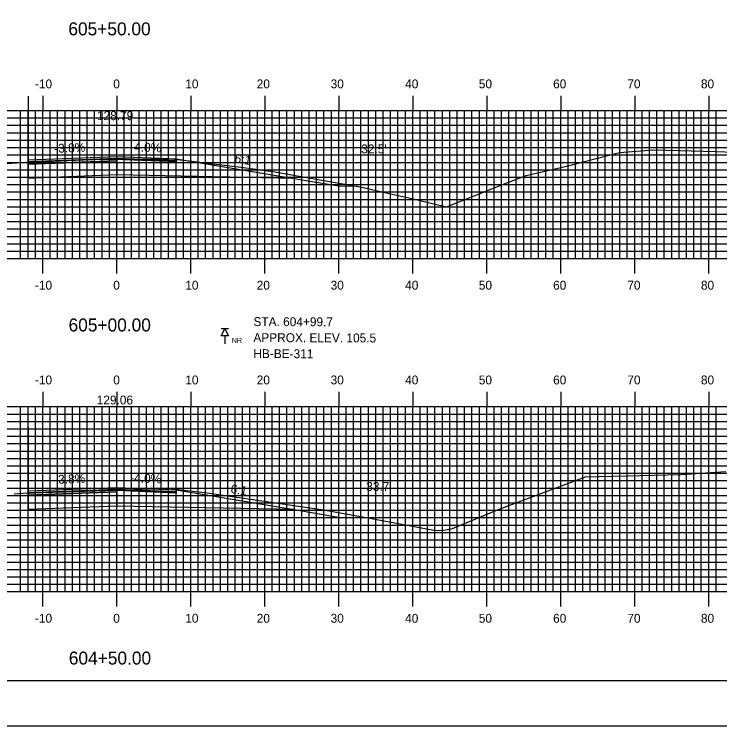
# Model space of a CAD drawing. Extents: x 842175 to 842518, y 363538 to 363758.
# Drawn here: x 842327 to 842422.4, y 363537.6 to 363633.7 of the extents above; entities that cross this region are included whole.
import ezdxf

# ---------------------------------------------------------------- set-up
doc = ezdxf.new("R2010")
doc.units = 0
for name, color, linetype in [('ANNOTATION', 7, 'Continuous'), ('BORDER', 7, 'Continuous'), ('BORING - NO REFUSAL', 7, 'Continuous'), ('D_Roadway_Centerline', 7, 'Continuous'), ('D_Roadway_Centerline_Text', 7, 'Continuous'), ('D_Roadway_Edge_Shoulder', 7, 'Continuous'), ('D_Roadway_Edge_TW', 7, 'Continuous'), ('D_Roadway_FinishedGrade', 7, 'Continuous'), ('D_Roadway_Pavement', 7, 'Continuous'), ('D_Roadway_SlopeLines', 7, 'Continuous'), ('D_Roadway_SubGrade', 7, 'Continuous'), ('D_Text_Standard', 7, 'Continuous'), ('H_V ANNOTATION', 7, 'Continuous'), ('M_Roadway_Centerline', 7, 'Continuous'), ('MAJOR', 7, 'Continuous'), ('MINOR', 7, 'Continuous'), ('PLOT BOUNDARY', 7, 'Continuous'), ('S_Roadway_Centerline', 7, 'Continuous')]:
    doc.layers.add(name, color=color, linetype=linetype)

msp = doc.modelspace()

# ---------------------------------------------------------------- linework, layer by layer
at = {"layer": 'BORDER'}
msp.add_lwpolyline([(842191.285, 363543.721), (842511.285, 363543.721), (842511.285, 363753.721), (842191.285, 363753.721)], close=True, dxfattribs=at)
at = {"layer": 'BORING - NO REFUSAL'}
for p, q in [((842355.965, 363591.221), (842355.005, 363591.221)), ((842355.485, 363590.261), (842355.485, 363589.202))]:
    msp.add_line(p, q, dxfattribs=at)
msp.add_lwpolyline([(842355.485, 363591.221), (842355.965, 363590.261), (842355.005, 363590.261)], close=True, dxfattribs=at)
at = {"layer": 'D_Roadway_Centerline'}
for points in [[(842328.885, 363614.056), (842340.885, 363614.512), (842348.885, 363614.192), (842349.971, 363614.011), (842364.839, 363611.533)], [(842328.885, 363569.328), (842340.885, 363569.784), (842348.885, 363569.464), (842364.839, 363566.805)]]:
    msp.add_lwpolyline(points, dxfattribs=at)
at = {"layer": 'D_Roadway_Edge_Shoulder'}
for points in [[(842340.885, 363614.512), (842348.885, 363614.192), (842348.885, 363613.942), (842340.885, 363614.262)], [(842340.885, 363569.784), (842348.885, 363569.464), (842348.885, 363569.214), (842340.885, 363569.534)]]:
    msp.add_lwpolyline(points, close=True, dxfattribs=at)
at = {"layer": 'D_Roadway_Edge_TW'}
for points in [[(842328.885, 363614.056), (842340.885, 363614.512), (842340.885, 363614.262), (842328.885, 363613.806)], [(842328.885, 363569.328), (842340.885, 363569.784), (842340.885, 363569.534), (842328.885, 363569.078)]]:
    msp.add_lwpolyline(points, close=True, dxfattribs=at)
for points in [[(842328.885, 363614.056), (842328.885, 363613.806)], [(842328.885, 363569.328), (842328.885, 363569.078)]]:
    msp.add_lwpolyline(points, dxfattribs=at)
at = {"layer": 'D_Roadway_FinishedGrade'}
for points in [[(842364.839, 363611.533), (842370.839, 363610.533), (842373.407, 363610.482)], [(842364.839, 363566.805), (842370.839, 363565.805), (842374.678, 363565.728)]]:
    msp.add_lwpolyline(points, dxfattribs=at)
at = {"layer": 'D_Roadway_Pavement'}
for points in [[(842328.885, 363613.806), (842340.885, 363614.262), (842340.885, 363613.929), (842328.885, 363613.473)], [(842340.885, 363614.262), (842348.885, 363613.942), (842348.885, 363613.776), (842340.885, 363614.096)], [(842328.885, 363569.078), (842340.885, 363569.534), (842340.885, 363569.201), (842328.885, 363568.745)], [(842340.885, 363569.534), (842348.885, 363569.214), (842348.885, 363569.047), (842340.885, 363569.367)]]:
    msp.add_lwpolyline(points, close=True, dxfattribs=at)
for points in [[(842328.885, 363613.806), (842328.885, 363613.473)], [(842340.885, 363614.262), (842340.885, 363613.929)], [(842340.885, 363614.262), (842340.885, 363613.929)], [(842340.885, 363569.534), (842340.885, 363569.201)], [(842340.885, 363569.534), (842340.885, 363569.201)], [(842328.885, 363569.078), (842328.885, 363568.745)]]:
    msp.add_lwpolyline(points, dxfattribs=at)
at = {"layer": 'D_Roadway_SlopeLines'}
msp.add_lwpolyline([(842348.885, 363614.192), (842349.971, 363614.011)], dxfattribs=at)
at = {"layer": 'D_Roadway_SubGrade'}
for p, q in [((842328.885, 363622.654), (842328.885, 363611.556)), ((842328.885, 363577.925), (842328.885, 363566.828))]:
    msp.add_line(p, q, dxfattribs=at)
for points in [[(842328.885, 363613.473), (842340.885, 363613.929), (842340.885, 363612.012), (842328.885, 363611.556)], [(842340.885, 363613.929), (842340.885, 363614.262), (842348.885, 363613.942), (842348.885, 363614.192), (842364.839, 363611.533), (842340.885, 363612.012)], [(842340.885, 363569.201), (842340.885, 363569.534), (842348.885, 363569.214), (842348.885, 363569.464), (842364.839, 363566.805), (842340.885, 363567.284)], [(842328.885, 363568.745), (842340.885, 363569.201), (842340.885, 363567.284), (842328.885, 363566.828)]]:
    msp.add_lwpolyline(points, close=True, dxfattribs=at)
for points in [[(842328.885, 363613.473), (842328.885, 363611.556)], [(842328.885, 363568.745), (842328.885, 363566.828)]]:
    msp.add_lwpolyline(points, dxfattribs=at)
at = {"layer": 'MAJOR'}
for p, q in [((842330.885, 363622.725), (842330.885, 363620.721)), ((842340.885, 363622.725), (842340.885, 363620.721)), ((842350.885, 363622.725), (842350.885, 363620.721)), ((842360.885, 363622.725), (842360.885, 363620.721)), ((842370.885, 363622.725), (842370.885, 363620.721)), ((842380.885, 363622.725), (842380.885, 363620.721)), ((842390.885, 363622.725), (842390.885, 363620.721)), ((842400.885, 363622.725), (842400.885, 363620.721)), ((842410.885, 363622.725), (842410.885, 363620.721)), ((842420.885, 363622.725), (842420.885, 363620.721)), ((842200.885, 363620.721), (842480.885, 363620.721)), ((842200.885, 363620.721), (842480.885, 363620.721)), ((842330.885, 363600.721), (842330.885, 363620.721)), ((842340.885, 363600.721), (842340.885, 363620.721)), ((842350.885, 363600.721), (842350.885, 363620.721)), ((842360.885, 363600.721), (842360.885, 363620.721)), ((842370.885, 363600.721), (842370.885, 363620.721)), ((842380.885, 363600.721), (842380.885, 363620.721)), ((842390.885, 363600.721), (842390.885, 363620.721)), ((842400.885, 363600.721), (842400.885, 363620.721)), ((842410.885, 363600.721), (842410.885, 363620.721)), ((842420.885, 363600.721), (842420.885, 363620.721)), ((842200.885, 363615.721), (842480.885, 363615.721)), ((842200.885, 363610.721), (842480.885, 363610.721)), ((842200.885, 363605.721), (842480.885, 363605.721)), ((842200.885, 363600.721), (842480.885, 363600.721)), ((842200.885, 363600.721), (842480.885, 363600.721)), ((842330.885, 363598.717), (842330.885, 363600.721)), ((842340.885, 363598.717), (842340.885, 363600.721)), ((842350.885, 363598.717), (842350.885, 363600.721)), ((842360.885, 363598.717), (842360.885, 363600.721)), ((842370.885, 363598.717), (842370.885, 363600.721)), ((842380.885, 363598.717), (842380.885, 363600.721)), ((842390.885, 363598.717), (842390.885, 363600.721)), ((842400.885, 363598.717), (842400.885, 363600.721)), ((842410.885, 363598.717), (842410.885, 363600.721)), ((842420.885, 363598.717), (842420.885, 363600.721)), ((842330.885, 363582.725), (842330.885, 363580.721)), ((842340.885, 363582.725), (842340.885, 363580.721)), ((842350.885, 363582.725), (842350.885, 363580.721)), ((842360.885, 363582.725), (842360.885, 363580.721)), ((842370.885, 363582.725), (842370.885, 363580.721)), ((842380.885, 363582.725), (842380.885, 363580.721)), ((842390.885, 363582.725), (842390.885, 363580.721)), ((842400.885, 363582.725), (842400.885, 363580.721)), ((842410.885, 363582.725), (842410.885, 363580.721)), ((842420.885, 363582.725), (842420.885, 363580.721)), ((842200.885, 363580.721), (842480.885, 363580.721)), ((842200.885, 363580.721), (842480.885, 363580.721)), ((842330.885, 363555.721), (842330.885, 363580.721)), ((842340.885, 363555.721), (842340.885, 363580.721)), ((842350.885, 363555.721), (842350.885, 363580.721)), ((842360.885, 363555.721), (842360.885, 363580.721)), ((842370.885, 363555.721), (842370.885, 363580.721)), ((842380.885, 363555.721), (842380.885, 363580.721)), ((842390.885, 363555.721), (842390.885, 363580.721)), ((842400.885, 363555.721), (842400.885, 363580.721)), ((842410.885, 363555.721), (842410.885, 363580.721)), ((842420.885, 363555.721), (842420.885, 363580.721)), ((842200.885, 363575.721), (842480.885, 363575.721)), ((842200.885, 363570.721), (842480.885, 363570.721)), ((842200.885, 363565.721), (842480.885, 363565.721)), ((842200.885, 363560.721), (842480.885, 363560.721)), ((842200.885, 363555.721), (842480.885, 363555.721)), ((842200.885, 363555.721), (842480.885, 363555.721)), ((842330.885, 363553.717), (842330.885, 363555.721)), ((842340.885, 363553.717), (842340.885, 363555.721)), ((842350.885, 363553.717), (842350.885, 363555.721)), ((842360.885, 363553.717), (842360.885, 363555.721)), ((842370.885, 363553.717), (842370.885, 363555.721)), ((842380.885, 363553.717), (842380.885, 363555.721)), ((842390.885, 363553.717), (842390.885, 363555.721)), ((842400.885, 363553.717), (842400.885, 363555.721)), ((842410.885, 363553.717), (842410.885, 363555.721)), ((842420.885, 363553.717), (842420.885, 363555.721))]:
    msp.add_line(p, q, dxfattribs=at)
at = {"layer": 'MINOR'}
for p, q in [((842327.885, 363600.721), (842327.885, 363620.721)), ((842328.885, 363600.721), (842328.885, 363620.721)), ((842329.885, 363600.721), (842329.885, 363620.721)), ((842331.885, 363600.721), (842331.885, 363620.721)), ((842332.885, 363600.721), (842332.885, 363620.721)), ((842333.885, 363600.721), (842333.885, 363620.721)), ((842334.885, 363600.721), (842334.885, 363620.721)), ((842335.885, 363600.721), (842335.885, 363620.721)), ((842336.885, 363600.721), (842336.885, 363620.721)), ((842337.885, 363600.721), (842337.885, 363620.721)), ((842338.885, 363600.721), (842338.885, 363620.721)), ((842339.885, 363600.721), (842339.885, 363620.721)), ((842341.885, 363600.721), (842341.885, 363620.721)), ((842342.885, 363600.721), (842342.885, 363620.721)), ((842343.885, 363600.721), (842343.885, 363620.721)), ((842344.885, 363600.721), (842344.885, 363620.721)), ((842345.885, 363600.721), (842345.885, 363620.721)), ((842346.885, 363600.721), (842346.885, 363620.721)), ((842347.885, 363600.721), (842347.885, 363620.721)), ((842348.885, 363600.721), (842348.885, 363620.721)), ((842349.885, 363600.721), (842349.885, 363620.721)), ((842351.885, 363600.721), (842351.885, 363620.721)), ((842352.885, 363600.721), (842352.885, 363620.721)), ((842353.885, 363600.721), (842353.885, 363620.721)), ((842354.885, 363600.721), (842354.885, 363620.721)), ((842355.885, 363600.721), (842355.885, 363620.721)), ((842356.885, 363600.721), (842356.885, 363620.721)), ((842357.885, 363600.721), (842357.885, 363620.721)), ((842358.885, 363600.721), (842358.885, 363620.721)), ((842359.885, 363600.721), (842359.885, 363620.721)), ((842361.885, 363600.721), (842361.885, 363620.721)), ((842362.885, 363600.721), (842362.885, 363620.721)), ((842363.885, 363600.721), (842363.885, 363620.721)), ((842364.885, 363600.721), (842364.885, 363620.721)), ((842365.885, 363600.721), (842365.885, 363620.721)), ((842366.885, 363600.721), (842366.885, 363620.721)), ((842367.885, 363600.721), (842367.885, 363620.721)), ((842368.885, 363600.721), (842368.885, 363620.721)), ((842369.885, 363600.721), (842369.885, 363620.721)), ((842371.885, 363600.721), (842371.885, 363620.721)), ((842372.885, 363600.721), (842372.885, 363620.721)), ((842373.885, 363600.721), (842373.885, 363620.721)), ((842374.885, 363600.721), (842374.885, 363620.721)), ((842375.885, 363600.721), (842375.885, 363620.721)), ((842376.885, 363600.721), (842376.885, 363620.721)), ((842377.885, 363600.721), (842377.885, 363620.721)), ((842378.885, 363600.721), (842378.885, 363620.721)), ((842379.885, 363600.721), (842379.885, 363620.721)), ((842381.885, 363600.721), (842381.885, 363620.721)), ((842382.885, 363600.721), (842382.885, 363620.721)), ((842383.885, 363600.721), (842383.885, 363620.721)), ((842384.885, 363600.721), (842384.885, 363620.721)), ((842385.885, 363600.721), (842385.885, 363620.721)), ((842386.885, 363600.721), (842386.885, 363620.721)), ((842387.885, 363600.721), (842387.885, 363620.721)), ((842388.885, 363600.721), (842388.885, 363620.721)), ((842389.885, 363600.721), (842389.885, 363620.721)), ((842391.885, 363600.721), (842391.885, 363620.721)), ((842392.885, 363600.721), (842392.885, 363620.721)), ((842393.885, 363600.721), (842393.885, 363620.721)), ((842394.885, 363600.721), (842394.885, 363620.721)), ((842395.885, 363600.721), (842395.885, 363620.721)), ((842396.885, 363600.721), (842396.885, 363620.721)), ((842397.885, 363600.721), (842397.885, 363620.721)), ((842398.885, 363600.721), (842398.885, 363620.721)), ((842399.885, 363600.721), (842399.885, 363620.721)), ((842401.885, 363600.721), (842401.885, 363620.721)), ((842402.885, 363600.721), (842402.885, 363620.721)), ((842403.885, 363600.721), (842403.885, 363620.721)), ((842404.885, 363600.721), (842404.885, 363620.721)), ((842405.885, 363600.721), (842405.885, 363620.721)), ((842406.885, 363600.721), (842406.885, 363620.721)), ((842407.885, 363600.721), (842407.885, 363620.721)), ((842408.885, 363600.721), (842408.885, 363620.721)), ((842409.885, 363600.721), (842409.885, 363620.721)), ((842411.885, 363600.721), (842411.885, 363620.721)), ((842412.885, 363600.721), (842412.885, 363620.721)), ((842413.885, 363600.721), (842413.885, 363620.721)), ((842414.885, 363600.721), (842414.885, 363620.721)), ((842415.885, 363600.721), (842415.885, 363620.721)), ((842416.885, 363600.721), (842416.885, 363620.721)), ((842417.885, 363600.721), (842417.885, 363620.721)), ((842418.885, 363600.721), (842418.885, 363620.721)), ((842419.885, 363600.721), (842419.885, 363620.721)), ((842421.885, 363600.721), (842421.885, 363620.721)), ((842200.885, 363619.721), (842480.885, 363619.721)), ((842200.885, 363618.721), (842480.885, 363618.721)), ((842200.885, 363617.721), (842480.885, 363617.721)), ((842200.885, 363616.721), (842480.885, 363616.721)), ((842200.885, 363614.721), (842480.885, 363614.721)), ((842200.885, 363613.721), (842480.885, 363613.721)), ((842200.885, 363612.721), (842480.885, 363612.721)), ((842200.885, 363611.721), (842480.885, 363611.721)), ((842200.885, 363609.721), (842480.885, 363609.721)), ((842200.885, 363608.721), (842480.885, 363608.721)), ((842200.885, 363607.721), (842480.885, 363607.721)), ((842200.885, 363606.721), (842480.885, 363606.721)), ((842200.885, 363604.721), (842480.885, 363604.721)), ((842200.885, 363603.721), (842480.885, 363603.721)), ((842200.885, 363602.721), (842480.885, 363602.721)), ((842200.885, 363601.721), (842480.885, 363601.721)), ((842327.885, 363555.721), (842327.885, 363580.721)), ((842328.885, 363555.721), (842328.885, 363580.721)), ((842329.885, 363555.721), (842329.885, 363580.721)), ((842331.885, 363555.721), (842331.885, 363580.721)), ((842332.885, 363555.721), (842332.885, 363580.721)), ((842333.885, 363555.721), (842333.885, 363580.721)), ((842334.885, 363555.721), (842334.885, 363580.721)), ((842335.885, 363555.721), (842335.885, 363580.721)), ((842336.885, 363555.721), (842336.885, 363580.721)), ((842337.885, 363555.721), (842337.885, 363580.721)), ((842338.885, 363555.721), (842338.885, 363580.721)), ((842339.885, 363555.721), (842339.885, 363580.721)), ((842341.885, 363555.721), (842341.885, 363580.721)), ((842342.885, 363555.721), (842342.885, 363580.721)), ((842343.885, 363555.721), (842343.885, 363580.721)), ((842344.885, 363555.721), (842344.885, 363580.721)), ((842345.885, 363555.721), (842345.885, 363580.721)), ((842346.885, 363555.721), (842346.885, 363580.721)), ((842347.885, 363555.721), (842347.885, 363580.721)), ((842348.885, 363555.721), (842348.885, 363580.721)), ((842349.885, 363555.721), (842349.885, 363580.721)), ((842351.885, 363555.721), (842351.885, 363580.721)), ((842352.885, 363555.721), (842352.885, 363580.721)), ((842353.885, 363555.721), (842353.885, 363580.721)), ((842354.885, 363555.721), (842354.885, 363580.721)), ((842355.885, 363555.721), (842355.885, 363580.721)), ((842356.885, 363555.721), (842356.885, 363580.721)), ((842357.885, 363555.721), (842357.885, 363580.721)), ((842358.885, 363555.721), (842358.885, 363580.721)), ((842359.885, 363555.721), (842359.885, 363580.721)), ((842361.885, 363555.721), (842361.885, 363580.721)), ((842362.885, 363555.721), (842362.885, 363580.721)), ((842363.885, 363555.721), (842363.885, 363580.721)), ((842364.885, 363555.721), (842364.885, 363580.721)), ((842365.885, 363555.721), (842365.885, 363580.721)), ((842366.885, 363555.721), (842366.885, 363580.721)), ((842367.885, 363555.721), (842367.885, 363580.721)), ((842368.885, 363555.721), (842368.885, 363580.721)), ((842369.885, 363555.721), (842369.885, 363580.721)), ((842371.885, 363555.721), (842371.885, 363580.721)), ((842372.885, 363555.721), (842372.885, 363580.721)), ((842373.885, 363555.721), (842373.885, 363580.721)), ((842374.885, 363555.721), (842374.885, 363580.721)), ((842375.885, 363555.721), (842375.885, 363580.721)), ((842376.885, 363555.721), (842376.885, 363580.721)), ((842377.885, 363555.721), (842377.885, 363580.721)), ((842378.885, 363555.721), (842378.885, 363580.721)), ((842379.885, 363555.721), (842379.885, 363580.721)), ((842381.885, 363555.721), (842381.885, 363580.721)), ((842382.885, 363555.721), (842382.885, 363580.721)), ((842383.885, 363555.721), (842383.885, 363580.721)), ((842384.885, 363555.721), (842384.885, 363580.721)), ((842385.885, 363555.721), (842385.885, 363580.721)), ((842386.885, 363555.721), (842386.885, 363580.721)), ((842387.885, 363555.721), (842387.885, 363580.721)), ((842388.885, 363555.721), (842388.885, 363580.721)), ((842389.885, 363555.721), (842389.885, 363580.721)), ((842391.885, 363555.721), (842391.885, 363580.721)), ((842392.885, 363555.721), (842392.885, 363580.721)), ((842393.885, 363555.721), (842393.885, 363580.721)), ((842394.885, 363555.721), (842394.885, 363580.721)), ((842395.885, 363555.721), (842395.885, 363580.721)), ((842396.885, 363555.721), (842396.885, 363580.721)), ((842397.885, 363555.721), (842397.885, 363580.721)), ((842398.885, 363555.721), (842398.885, 363580.721)), ((842399.885, 363555.721), (842399.885, 363580.721)), ((842401.885, 363555.721), (842401.885, 363580.721)), ((842402.885, 363555.721), (842402.885, 363580.721)), ((842403.885, 363555.721), (842403.885, 363580.721)), ((842404.885, 363555.721), (842404.885, 363580.721)), ((842405.885, 363555.721), (842405.885, 363580.721)), ((842406.885, 363555.721), (842406.885, 363580.721)), ((842407.885, 363555.721), (842407.885, 363580.721)), ((842408.885, 363555.721), (842408.885, 363580.721)), ((842409.885, 363555.721), (842409.885, 363580.721)), ((842411.885, 363555.721), (842411.885, 363580.721)), ((842412.885, 363555.721), (842412.885, 363580.721)), ((842413.885, 363555.721), (842413.885, 363580.721)), ((842414.885, 363555.721), (842414.885, 363580.721)), ((842415.885, 363555.721), (842415.885, 363580.721)), ((842416.885, 363555.721), (842416.885, 363580.721)), ((842417.885, 363555.721), (842417.885, 363580.721)), ((842418.885, 363555.721), (842418.885, 363580.721)), ((842419.885, 363555.721), (842419.885, 363580.721)), ((842421.885, 363555.721), (842421.885, 363580.721)), ((842200.885, 363579.721), (842480.885, 363579.721)), ((842200.885, 363578.721), (842480.885, 363578.721)), ((842200.885, 363577.721), (842480.885, 363577.721)), ((842200.885, 363576.721), (842480.885, 363576.721)), ((842200.885, 363574.721), (842480.885, 363574.721)), ((842200.885, 363573.721), (842480.885, 363573.721)), ((842200.885, 363572.721), (842480.885, 363572.721)), ((842200.885, 363571.721), (842480.885, 363571.721)), ((842200.885, 363569.721), (842480.885, 363569.721)), ((842200.885, 363568.721), (842480.885, 363568.721)), ((842200.885, 363567.721), (842480.885, 363567.721)), ((842200.885, 363566.721), (842480.885, 363566.721)), ((842200.885, 363564.721), (842480.885, 363564.721)), ((842200.885, 363563.721), (842480.885, 363563.721)), ((842200.885, 363562.721), (842480.885, 363562.721)), ((842200.885, 363561.721), (842480.885, 363561.721)), ((842200.885, 363559.721), (842480.885, 363559.721)), ((842200.885, 363558.721), (842480.885, 363558.721)), ((842200.885, 363557.721), (842480.885, 363557.721)), ((842200.885, 363556.721), (842480.885, 363556.721))]:
    msp.add_line(p, q, dxfattribs=at)
at = {"layer": 'PLOT BOUNDARY'}
msp.add_lwpolyline([(842175.098, 363537.603), (842515.098, 363537.603), (842515.098, 363757.603), (842175.098, 363757.603)], close=True, dxfattribs=at)
at = {"layer": 'S_Roadway_Centerline'}
for points in [[(842324.041, 363613.441), (842328.696, 363613.749), (842329.192, 363613.74), (842336.381, 363614.073), (842338.842, 363614.155), (842339.179, 363614.126), (842348.222, 363614.197), (842350.68, 363613.936), (842358.011, 363613.015), (842361.975, 363612.464), (842368.617, 363611.3), (842374.019, 363610.378), (842377.098, 363609.641), (842380.78, 363608.817), (842385.434, 363607.708), (842393.144, 363610.774), (842396.206, 363611.964), (842401.467, 363613.143), (842408.822, 363615.055), (842413.485, 363615.431), (842421.873, 363615.203), (842432.992, 363614.789)], [(842327.004, 363568.95), (842328.764, 363569.069), (842329.007, 363569.025), (842330.948, 363569.118), (842342.163, 363569.479), (842347.466, 363569.684), (842347.957, 363569.682), (842348.856, 363569.578), (842353.091, 363569.061), (842358.648, 363568.264), (842368.841, 363566.766), (842374.595, 363565.743), (842383.719, 363564.016), (842384.8, 363563.963), (842386.248, 363564.247), (842392.559, 363566.853), (842404.236, 363571.248), (842417.157, 363571.568), (842423.219, 363571.957)]]:
    msp.add_lwpolyline(points, dxfattribs=at)

# ---------------------------------------------------------------- texts
at = {"layer": 'ANNOTATION'}
for s, rotation, p in [('-3.8%', 2.17619, (842332.446, 363614.993)), ('-4.0%', 357.70939, (842342.677, 363615.242)), ('6:1', 350.53749, (842356.738, 363613.711)), ('-3.8%', 2.17619, (842332.446, 363570.265)), ('-4.0%', 357.70939, (842342.677, 363570.514)), ('6:1', 350.53749, (842356.195, 363569.073))]:
    msp.add_text(s, height=1.2, rotation=rotation, dxfattribs=at).set_placement(p)
at = {"layer": 'BORING - NO REFUSAL'}
for s, p in [('STA. 604+99.7', (842359.352, 363591.606)), ('APPROX. ELEV. 105.5', (842359.345, 363589.446)), ('HB-BE-311', (842359.338, 363587.286))]:
    msp.add_text(s, height=1.2, rotation=359.81416, dxfattribs=at).set_placement(p)
msp.add_text('NR', height=0.6998, dxfattribs=at).set_placement((842356.418, 363589.306))
at = {"layer": 'D_Roadway_Centerline_Text'}
for s, p in [('128.79', (842338.199, 363619.422)), ('129.06', (842338.167, 363581.011))]:
    msp.add_text(s, height=1.2, dxfattribs=at).set_placement(p)
at = {"layer": 'D_Text_Standard'}
for s, p in [("32.5'", (842373.921, 363614.935)), ("33.7'", (842374.6, 363569.337))]:
    msp.add_text(s, height=1.2, dxfattribs=at).set_placement(p)
at = {"layer": 'H_V ANNOTATION'}
for s, height, p in [('605+50.00', 1.75, (842334.33, 363630.877)), ('-10', 1.2, (842329.815, 363623.721)), ('0', 1.2, (842340.403, 363623.721)), ('10', 1.2, (842350.136, 363623.721)), ('20', 1.2, (842359.793, 363623.721)), ('30', 1.2, (842369.782, 363623.721)), ('40', 1.2, (842379.857, 363623.721)), ('50', 1.2, (842389.814, 363623.721)), ('60', 1.2, (842399.857, 363623.721)), ('70', 1.2, (842409.889, 363623.721)), ('80', 1.2, (842419.836, 363623.721)), ('-10', 1.2, (842329.815, 363596.521)), ('0', 1.2, (842340.403, 363596.521)), ('10', 1.2, (842350.136, 363596.521)), ('20', 1.2, (842359.793, 363596.521)), ('30', 1.2, (842369.782, 363596.521)), ('40', 1.2, (842379.857, 363596.521)), ('50', 1.2, (842389.814, 363596.521)), ('60', 1.2, (842399.857, 363596.521)), ('70', 1.2, (842409.889, 363596.521)), ('80', 1.2, (842419.836, 363596.521)), ('605+00.00', 1.75, (842334.361, 363590.877)), ('-10', 1.2, (842329.815, 363583.721)), ('0', 1.2, (842340.403, 363583.721)), ('10', 1.2, (842350.136, 363583.721)), ('20', 1.2, (842359.793, 363583.721)), ('30', 1.2, (842369.782, 363583.721)), ('40', 1.2, (842379.857, 363583.721)), ('50', 1.2, (842389.814, 363583.721)), ('60', 1.2, (842399.857, 363583.721)), ('70', 1.2, (842409.889, 363583.721)), ('80', 1.2, (842419.836, 363583.721)), ('-10', 1.2, (842329.815, 363551.521)), ('0', 1.2, (842340.403, 363551.521)), ('10', 1.2, (842350.136, 363551.521)), ('20', 1.2, (842359.793, 363551.521)), ('30', 1.2, (842369.782, 363551.521)), ('40', 1.2, (842379.857, 363551.521)), ('50', 1.2, (842389.814, 363551.521)), ('60', 1.2, (842399.857, 363551.521)), ('70', 1.2, (842409.889, 363551.521)), ('80', 1.2, (842419.836, 363551.521)), ('604+50.00', 1.75, (842334.393, 363545.877))]:
    msp.add_text(s, height=height, dxfattribs=at).set_placement(p)
at = {"layer": 'M_Roadway_Centerline'}
for s, p in [('C', (842328.691, 363613.749)), ('L', (842328.696, 363613.742)), ('C', (842328.758, 363569.069)), ('L', (842328.764, 363569.061))]:
    msp.add_text(s, height=0.0146, dxfattribs=at).set_placement(p)

doc.saveas('drawing.dxf')
